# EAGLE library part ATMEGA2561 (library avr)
MICROCONTROLLER 256 Kbytes FLASH 8 Kbytes SRAM 4 Kbytes EEPROM DUAL USART 8-channel 10 bit ADC
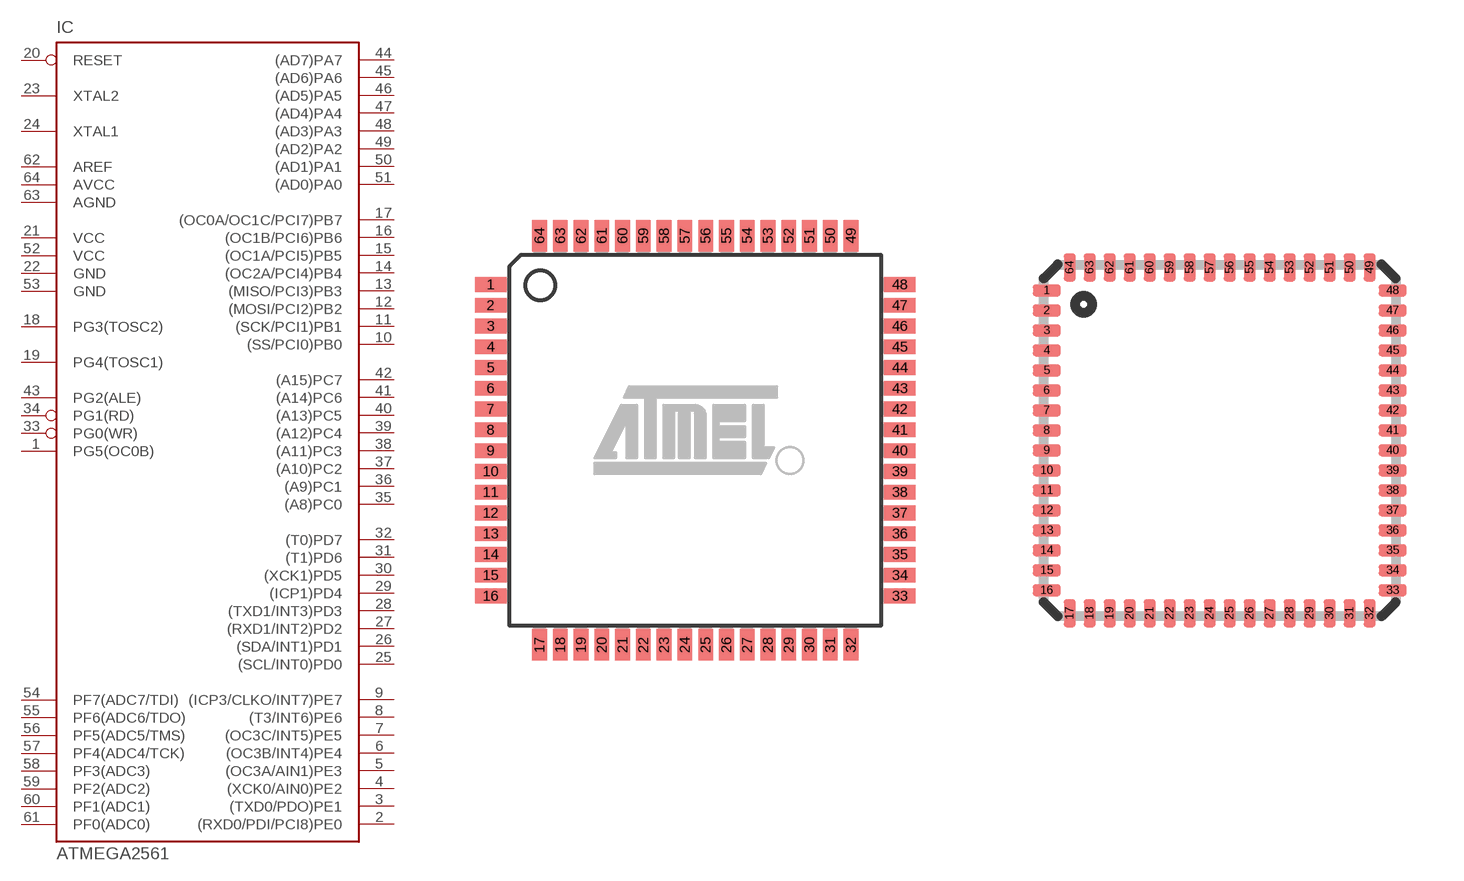
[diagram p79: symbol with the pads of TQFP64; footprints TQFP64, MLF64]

Designator prefix IC

## ATMEGA2561-16A, ATMEGA2561V-8A  [TQFP64]
1  PG5(OC0B)
2  (RXD0/PDI/PCI8)PE0
3  (TXD0/PDO)PE1
4  (XCK0/AIN0)PE2
5  (OC3A/AIN1)PE3
6  (OC3B/INT4)PE4
7  (OC3C/INT5)PE5
8  (T3/INT6)PE6
9  (ICP3/CLKO/INT7)PE7
10  (SS/PCI0)PB0
11  (SCK/PCI1)PB1
12  (MOSI/PCI2)PB2
13  (MISO/PCI3)PB3
14  (OC2A/PCI4)PB4
15  (OC1A/PCI5)PB5
16  (OC1B/PCI6)PB6
17  (OC0A/OC1C/PCI7)PB7
18  PG3(TOSC2)
19  PG4(TOSC1)
20  RESET  in
21  VCC  pwr
22  GND  pwr
23  XTAL2
24  XTAL1
25  (SCL/INT0)PD0
26  (SDA/INT1)PD1
27  (RXD1/INT2)PD2
28  (TXD1/INT3)PD3
29  (ICP1)PD4
30  (XCK1)PD5
31  (T1)PD6
32  (T0)PD7
33  PG0(WR)
34  PG1(RD)
35  (A8)PC0
36  (A9)PC1
37  (A10)PC2
38  (A11)PC3
39  (A12)PC4
40  (A13)PC5
41  (A14)PC6
42  (A15)PC7
43  PG2(ALE)
44  (AD7)PA7
45  (AD6)PA6
46  (AD5)PA5
47  (AD4)PA4
48  (AD3)PA3
49  (AD2)PA2
50  (AD1)PA1
51  (AD0)PA0
52  VCC  pwr
53  GND  pwr
54  PF7(ADC7/TDI)  in
55  PF6(ADC6/TDO)  in
56  PF5(ADC5/TMS)  in
57  PF4(ADC4/TCK)  in
58  PF3(ADC3)  in
59  PF2(ADC2)  in
60  PF1(ADC1)  in
61  PF0(ADC0)  in
62  AREF  pwr
63  AGND  pwr
64  AVCC  pwr

## ATMEGA2561-16M, ATMEGA2561V-8M  [MLF64]
Pads as for TQFP64

## Footprint TQFP64 (pad centres in mm)
Thin Plasic Quad Flat Package
smd 1.194 x 0.559: 1 -7.76,5.905; 2 -7.76,5.118; 3 -7.76,4.331; 4 -7.76,3.543; 5 -7.76,2.756; 6 -7.76,1.968; 7 -7.76,1.181; 8 -7.76,0.394; 9 -7.76,-0.394; 10 -7.76,-1.181; 11 -7.76,-1.968; 12 -7.76,-2.756; 13 -7.76,-3.543; 14 -7.76,-4.331; 15 -7.76,-5.118; 16 -7.76,-5.905; 33 7.76,-5.905; 34 7.76,-5.118; 35 7.76,-4.331; 36 7.76,-3.543; 37 7.76,-2.756; 38 7.76,-1.968; 39 7.76,-1.181; 40 7.76,-0.394; 41 7.76,0.394; 42 7.76,1.181; 43 7.76,1.968; 44 7.76,2.756; 45 7.76,3.543; 46 7.76,4.331; 47 7.76,5.118; 48 7.76,5.905
smd 0.559 x 1.194: 17 -5.905,-7.76; 18 -5.118,-7.76; 19 -4.331,-7.76; 20 -3.543,-7.76; 21 -2.756,-7.76; 22 -1.968,-7.76; 23 -1.181,-7.76; 24 -0.394,-7.76; 25 0.394,-7.76; 26 1.181,-7.76; 27 1.968,-7.76; 28 2.756,-7.76; 29 3.543,-7.76; 30 4.331,-7.76; 31 5.118,-7.76; 32 5.905,-7.76; 49 5.905,7.76; 50 5.118,7.76; 51 4.331,7.76; 52 3.543,7.76; 53 2.756,7.76; 54 1.968,7.76; 55 1.181,7.76; 56 0.394,7.76; 57 -0.394,7.76; 58 -1.181,7.76; 59 -1.968,7.76; 60 -2.756,7.76; 61 -3.543,7.76; 62 -4.331,7.76; 63 -5.118,7.76; 64 -5.905,7.76

## Footprint MLF64 (pad centres in mm)
64M1 Micro Lead Frame package (MLF)
smd 0.7 x 0.3: 1 -4.325,3.75; 2 -4.325,3.25; 3 -4.325,2.75; 4 -4.325,2.25; 5 -4.325,1.75; 6 -4.325,1.25; 7 -4.325,0.75; 8 -4.325,0.25; 9 -4.325,-0.25; 10 -4.325,-0.75; 11 -4.325,-1.25; 12 -4.325,-1.75; 13 -4.325,-2.25; 14 -4.325,-2.75; 15 -4.325,-3.25; 16 -4.325,-3.75; 33 4.325,-3.75; 34 4.325,-3.25; 35 4.325,-2.75; 36 4.325,-2.25; 37 4.325,-1.75; 38 4.325,-1.25; 39 4.325,-0.75; 40 4.325,-0.25; 41 4.325,0.25; 42 4.325,0.75; 43 4.325,1.25; 44 4.325,1.75; 45 4.325,2.25; 46 4.325,2.75; 47 4.325,3.25; 48 4.325,3.75
smd 0.3 x 0.7: 17 -3.75,-4.325; 18 -3.25,-4.325; 19 -2.75,-4.325; 20 -2.25,-4.325; 21 -1.75,-4.325; 22 -1.25,-4.325; 23 -0.75,-4.325; 24 -0.25,-4.325; 25 0.25,-4.325; 26 0.75,-4.325; 27 1.25,-4.325; 28 1.75,-4.325; 29 2.25,-4.325; 30 2.75,-4.325; 31 3.25,-4.325; 32 3.75,-4.325; 49 3.75,4.325; 50 3.25,4.325; 51 2.75,4.325; 52 2.25,4.325; 53 1.75,4.325; 54 1.25,4.325; 55 0.75,4.325; 56 0.25,4.325; 57 -0.25,4.325; 58 -0.75,4.325; 59 -1.25,4.325; 60 -1.75,4.325; 61 -2.25,4.325; 62 -2.75,4.325; 63 -3.25,4.325; 64 -3.75,4.325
